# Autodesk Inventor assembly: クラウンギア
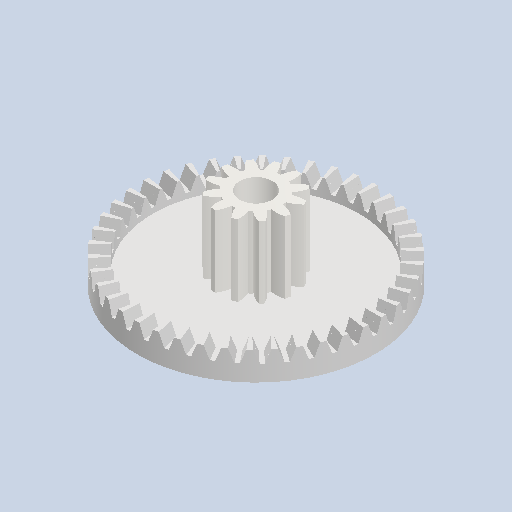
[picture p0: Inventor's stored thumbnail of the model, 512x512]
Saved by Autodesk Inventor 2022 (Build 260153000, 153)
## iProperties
Created: 2024-12
Part Number: クラウンギア
Document SubType Name: Assembly
Designer: jsat7
Author: jsat7
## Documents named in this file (3)
- C:\Users\jsat7\OneDrive\デスクトップ\卒論2024\３DCAD\自在ギヤボックス\部品図\クラウンギア.iam
- C:\Users\jsat7\OneDrive\デスクトップ\卒論2024\３DCAD\自在ギヤボックス\部品図\クラウンギア 土台.ipt
- C:\Users\jsat7\OneDrive\デスクトップ\卒論2024\３DCAD\自在ギヤボックス\部品図\12Tギア　クラウンギア.ipt
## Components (2 placed, 2 different names)
1. クラウンギア 土台:1 — リジッド:1
2. 平歯車1:1 — リジッド:1
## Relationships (1: WeldJoint 1)
- リジッド:1 [WeldJoint]: クラウンギア 土台:1 ↔ 平歯車1:1
